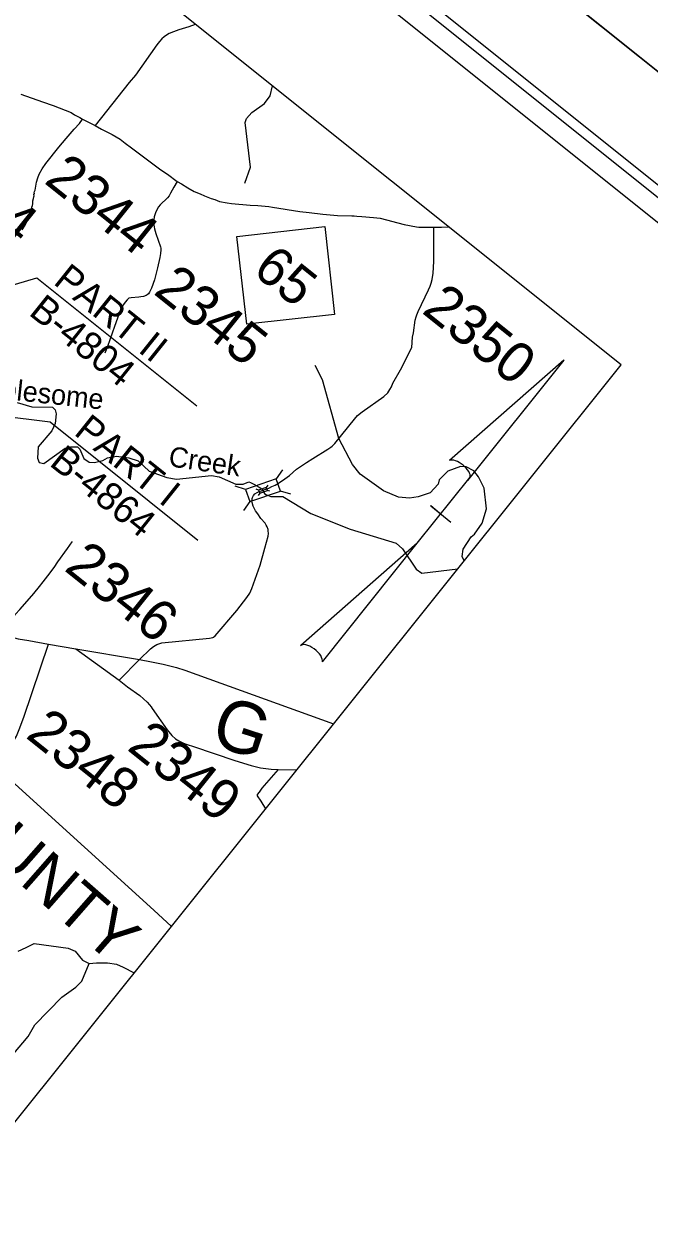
# Model space of a CAD drawing. Extents: x 1730256 to 1738218, y 910410 to 917906.
# Drawn here: x 1734658 to 1734975, y 916477 to 917081 of the extents above; entities that cross this region are included whole.
import ezdxf

# ---------------------------------------------------------------- set-up
doc = ezdxf.new("R2010")
doc.units = 0
for name, color, linetype in [('Old_Level_23', 7, 'Continuous'), ('Old_Level_24', 7, 'Continuous'), ('Old_Level_28', 7, 'Continuous'), ('Old_Level_29', 7, 'Continuous'), ('Old_Level_32', 7, 'Continuous'), ('Old_Level_50', 7, 'Continuous'), ('Old_Level_52', 7, 'Continuous'), ('Old_Level_56', 7, 'Continuous'), ('Old_Level_57', 7, 'Continuous'), ('Old_Level_59', 7, 'Continuous'), ('Old_Level_9', 7, 'Continuous'), ('Prop North Arrow for Plan Sheets CELL', 7, 'Continuous'), ('Sheet Cutting Line CELL', 7, 'Continuous'), ('Sheet Data Field CELL', 7, 'Continuous'), ('Sheet Plot Border Inside CELL', 7, 'Continuous'), ('Sheet Title CELL', 7, 'Continuous')]:
    doc.layers.add(name, color=color, linetype=linetype)

msp = doc.modelspace()

# ---------------------------------------------------------------- linework, layer by layer
at = {"layer": 'Old_Level_24'}
for p, q in [((1734570.37, 916923.86), (1734664.5, 916951.6)), ((1734664.5, 916951.6), (1734745.76, 916886.57)), ((1734645.29, 916881.7), (1734671.38, 916878.41)), ((1734671.38, 916878.41), (1734746.37, 916818.39))]:
    msp.add_line(p, q, dxfattribs=at)
at = {"layer": 'Old_Level_28'}
for p, q in [((1734670.48, 916765.5), (1734684.38, 916763.24)), ((1734684.38, 916763.24), (1734716.61, 916757.8))]:
    msp.add_line(p, q, dxfattribs=at)
for points in [[(1734649.58, 916769.56), (1734651.27, 916769.17), (1734653.25, 916768.74), (1734655.11, 916768.3), (1734660.49, 916767.38), (1734670.48, 916765.5)], [(1734716.61, 916757.8), (1734722.77, 916756.59), (1734728.66, 916755.34), (1734735.44, 916753.62), (1734739.63, 916752.34), (1734815.22, 916725.09)]]:
    msp.add_lwpolyline(points, dxfattribs=at)
at = {"layer": 'Old_Level_29'}
msp.add_line((1734687.79, 917032.17), (1734694.14, 917028.85), dxfattribs=at)
for points in [[(1734656.47, 917044.85), (1734667.42, 917040.88), (1734672.9, 917039.05), (1734682.02, 917035.47), (1734683.76, 917034.39), (1734685.75, 917033.33), (1734686.4, 917033.01), (1734687.79, 917032.17)], [(1734694.14, 917028.85), (1734697.47, 917027.12), (1734702.81, 917024.41), (1734706.94, 917021.89), (1734709.39, 917019.92), (1734712.61, 917017.63), (1734727.58, 917006.42), (1734730.93, 917004.11), (1734735.82, 917000.48)], [(1734735.82, 917000.48), (1734738.04, 916999.28), (1734741.17, 916997.25), (1734744.41, 916995.45), (1734747.4, 916994.22), (1734749.64, 916993.23), (1734753.05, 916991.88), (1734755, 916991.26), (1734757.36, 916990.38), (1734761.15, 916989.56), (1734763.35, 916989.26), (1734772.81, 916988.52), (1734776.74, 916988.29), (1734782.28, 916987.82), (1734784.2, 916987.5), (1734798.14, 916985.3), (1734802.84, 916984.66), (1734809.67, 916983.92), (1734817.25, 916983.26), (1734824.5, 916982.98), (1734825.72, 916983.04), (1734827.04, 916982.92), (1734829.5, 916982.77), (1734835.54, 916982.25), (1734838.76, 916981.78), (1734850.96, 916978.66), (1734857.25, 916977.39), (1734858.43, 916977.25), (1734860.37, 916977.24), (1734863.39, 916977.35), (1734866.02, 916977.35)], [(1734866.02, 916977.35), (1734869.92, 916977.34), (1734873.5, 916977.51)]]:
    msp.add_lwpolyline(points, dxfattribs=at)
at = {"layer": 'Old_Level_32'}
for p, q in [((1734684.38, 916763.24), (1734706.36, 916747.23)), ((1734706.36, 916747.23), (1734716.61, 916757.8))]:
    msp.add_line(p, q, dxfattribs=at)
for points in [[(1734745.1, 917080.26), (1734744.88, 917080.18), (1734741.69, 917079.04), (1734736.73, 917077.49), (1734733.94, 917076.53), (1734731.8, 917075.58), (1734730.38, 917074.8), (1734729.26, 917073.98), (1734727.98, 917072.89), (1734726.8, 917071.53), (1734725.55, 917069.91), (1734714.57, 917054.48), (1734711.49, 917050.65), (1734694.14, 917028.85)], [(1734657.17, 916975.93), (1734658.6, 916978.3), (1734659.79, 916980.86), (1734660.8, 916983.19), (1734661.66, 916985.45), (1734662.08, 916987.4), (1734662.29, 916988.27), (1734662.46, 916989.18), (1734662.62, 916990.57), (1734662.86, 916991.81), (1734663.03, 916992.62), (1734663.17, 916993.27), (1734663.1, 916993.9), (1734663.31, 916994.39), (1734663.29, 916995.08), (1734663.64, 916996.12), (1734664.39, 917000.1), (1734665.13, 917002.25), (1734665.8, 917004.23), (1734667.2, 917006.88), (1734669.07, 917009.64), (1734675.67, 917017.86), (1734679.46, 917022.32), (1734683.54, 917026.98), (1734686.24, 917029.88), (1734687.79, 917032.17)], [(1734735.82, 917000.48), (1734734.14, 916997.57), (1734732.5, 916994.46), (1734731.66, 916993.2), (1734730.94, 916992.25), (1734727.22, 916988.57), (1734726.4, 916987.57), (1734725.47, 916986.12), (1734724.74, 916984.53), (1734724.17, 916982.48), (1734723.91, 916980.75), (1734723.97, 916978.38), (1734724.32, 916976.35), (1734724.95, 916974.04), (1734727.37, 916967.21), (1734727.46, 916966.54), (1734727.48, 916965.69), (1734727.3, 916963.9), (1734726.94, 916961.87), (1734725.86, 916956.68), (1734724.3, 916950.53), (1734722.75, 916946.3), (1734721.98, 916944.61), (1734721.77, 916944.32), (1734721.2, 916943.5), (1734720.55, 916942.88), (1734720.04, 916942.57), (1734718.76, 916942.14), (1734717.32, 916941.86), (1734716.3, 916941.71), (1734712.52, 916941.43), (1734711.33, 916941.19), (1734710.9, 916940.89), (1734710.36, 916940.42), (1734709.42, 916939.27), (1734708.59, 916938), (1734707.79, 916936.52), (1734707.11, 916935.14), (1734706.37, 916933.36), (1734704.02, 916926.76), (1734700.5, 916916.75), (1734699.08, 916913.27)], [(1734779.36, 916843.69), (1734782.29, 916844.78), (1734783.86, 916845.54), (1734785.6, 916846.21), (1734787.8, 916847.57), (1734790.49, 916849.48), (1734792.76, 916851.13), (1734796.45, 916854.46), (1734801.42, 916857.84), (1734804.66, 916859.84), (1734812.33, 916864.58), (1734813.76, 916865.57), (1734814.4, 916866.12), (1734815.77, 916867.51), (1734825.74, 916879.81), (1734827.39, 916881.61), (1734829.68, 916883.49), (1734840.72, 916891.34), (1734842.79, 916893.08), (1734843.72, 916894.81), (1734844.57, 916896.15), (1734845.25, 916898.02), (1734849.09, 916904.76), (1734855, 916916.22), (1734855.27, 916921.51), (1734855.8, 916923.67), (1734856.67, 916930.11), (1734857.07, 916931.72), (1734857.42, 916932.79), (1734858.09, 916934.49), (1734863.39, 916945.52), (1734864.2, 916947.31), (1734864.79, 916948.9), (1734865.21, 916950.69), (1734865.69, 916953.9), (1734866.1, 916959.88), (1734866.02, 916977.35)], [(1734716.61, 916757.8), (1734722.19, 916763.15), (1734723.71, 916764.38), (1734725.49, 916765.37), (1734728.06, 916766.16), (1734752.26, 916768.53), (1734753.84, 916768.92), (1734754.31, 916769.12), (1734755.13, 916769.81), (1734766.14, 916782.63), (1734771.24, 916789.27), (1734772.66, 916791.5), (1734773.71, 916793.75), (1734777.99, 916805.59), (1734780.31, 916814.31), (1734781.92, 916820.33), (1734782.11, 916821.71), (1734782.07, 916823.09), (1734781.91, 916823.85), (1734781.46, 916825.13), (1734781.01, 916826), (1734780.41, 916826.94), (1734778.3, 916829.41), (1734776.7, 916831.66), (1734775.61, 916833.33), (1734774.71, 916834.99), (1734774.41, 916835.57), (1734773.79, 916837.52), (1734773.74, 916838.23), (1734773.82, 916838.99), (1734773.94, 916839.48), (1734774.08, 916840.03), (1734774.52, 916841.05), (1734775.21, 916841.83), (1734776.36, 916842.64), (1734777.41, 916843.08), (1734778.66, 916843.45), (1734779.36, 916843.69)], [(1734649.58, 916769.56), (1734650.6, 916773.17), (1734651.13, 916775.31), (1734652.47, 916778.8), (1734653.04, 916779.81), (1734653.78, 916780.83), (1734655.89, 916783.23), (1734660.86, 916788.67), (1734663.01, 916791.22), (1734665.92, 916794.89), (1734667.71, 916797.15), (1734670.18, 916800.27), (1734673.33, 916804.41), (1734675.28, 916807.28), (1734680.06, 916814.04), (1734682.48, 916817.5), (1734682.49, 916817.63)], [(1734641.87, 916706.48), (1734645.34, 916707.26), (1734648.22, 916709.96), (1734649.41, 916711.45), (1734650.29, 916712.68), (1734651.67, 916714.53), (1734654.31, 916718.84), (1734655.58, 916722.21), (1734657.9, 916728.49), (1734670.48, 916765.5)], [(1734706.36, 916747.23), (1734710.59, 916743.95), (1734716.93, 916739.46), (1734720.52, 916736.09), (1734721.74, 916734.78), (1734722.52, 916733.81), (1734723.15, 916732.91), (1734730.73, 916721.98), (1734733.07, 916719.12), (1734734.98, 916717.5), (1734736.6, 916716.44), (1734738.96, 916715.29), (1734740.95, 916714.57), (1734744.05, 916713.52), (1734765, 916706.43), (1734773.28, 916703.92), (1734778.06, 916702.74), (1734783.53, 916702.03), (1734787.09, 916701.97)], [(1734787.09, 916701.97), (1734778.86, 916692.42), (1734777.46, 916690.47), (1734776.48, 916689.25), (1734776.39, 916688.56), (1734778.22, 916685.86), (1734780.71, 916681.98)], [(1734787.09, 916701.97), (1734796.53, 916701.75)]]:
    msp.add_lwpolyline(points, dxfattribs=at)
at = {"layer": 'Old_Level_50'}
for p, q in [((1734789.28, 916854.02), (1734786.05, 916849.47)), ((1734770.54, 916844.12), (1734765.19, 916845.72)), ((1734781.84, 916846.28), (1734781.04, 916845.14)), ((1734777.16, 916843.8), (1734775.82, 916844.2)), ((1734777.69, 916842.25), (1734776.89, 916841.11)), ((1734782.91, 916843.19), (1734781.57, 916843.59)), ((1734793.54, 916841.67), (1734788.19, 916843.27)), ((1734772.68, 916837.92), (1734769.45, 916833.37))]:
    msp.add_line(p, q, dxfattribs=at)
msp.add_lwpolyline([(1734772.68, 916837.92), (1734788.19, 916843.27), (1734786.05, 916849.47), (1734770.54, 916844.12)], close=True, dxfattribs=at)
msp.add_lwpolyline([(1734777.69, 916842.25), (1734781.57, 916843.59), (1734781.04, 916845.14), (1734777.16, 916843.8), (1734777.69, 916842.25)], dxfattribs=at)
at = {"layer": 'Old_Level_52'}
msp.add_lwpolyline([(1734732.93, 916622.27), (1734723.88, 916630.49), (1734583.09, 916758.4), (1734358.65, 916958.62), (1734222.3, 917078.43)], dxfattribs=at)
at = {"layer": 'Old_Level_59'}
for points in [[(1734770.17, 916999.54), (1734773.05, 917007.71), (1734770.31, 917030.4), (1734770.98, 917032.52), (1734773.63, 917035.43), (1734780.15, 917040.14), (1734783.01, 917043.96), (1734784.19, 917048.99)], [(1734881.4, 916807.8), (1734880.55, 916809.98), (1734880.92, 916813.73), (1734885, 916820.05), (1734886.81, 916821.32), (1734890.64, 916826.99), (1734892.84, 916834.34), (1734891.65, 916844.74), (1734888.82, 916850.52), (1734886.46, 916853.56), (1734882.53, 916855.66), (1734879.69, 916855.79), (1734873.13, 916853.36), (1734868.82, 916849.05), (1734868.32, 916846.79), (1734864.16, 916842.35), (1734858.19, 916840.28), (1734853.66, 916839.68), (1734848.13, 916840.13), (1734840.54, 916843.36), (1734828.66, 916851.89), (1734824.8, 916856.71), (1734817.82, 916869.91), (1734809.59, 916899.75), (1734805.84, 916907.04)], [(1734654.66, 916888.29), (1734662.01, 916886.11), (1734672.56, 916885.85), (1734673.85, 916884.46), (1734674.34, 916882.44), (1734673.84, 916877.52), (1734672.14, 916873.8), (1734665.24, 916865.67), (1734664.94, 916860.05), (1734665.76, 916857.75), (1734668.05, 916857.24), (1734678.95, 916865.03), (1734681.69, 916865.73), (1734685.22, 916865.78), (1734686.4, 916864.58), (1734688.36, 916859.74), (1734691.19, 916857.91), (1734693.77, 916857.79), (1734698.07, 916858.79), (1734700.48, 916860.09), (1734704.96, 916860.96), (1734711.3, 916860.15), (1734716.01, 916858.68), (1734721.6, 916853.38)], [(1734721.6, 916853.38), (1734730.51, 916850.11), (1734735.47, 916849.28), (1734753.2, 916851.26), (1734757.11, 916850.46), (1734765.66, 916846.74), (1734769.24, 916846.86), (1734772.22, 916847.9), (1734773.05, 916847.69), (1734774.71, 916846.81), (1734777.46, 916845.27), (1734778.7, 916844.38), (1734779.36, 916843.69), (1734779.7, 916842.92), (1734780.17, 916841.99), (1734780.76, 916841.47), (1734783.36, 916840.45), (1734789.41, 916840.61), (1734803.6, 916831.97), (1734823.7, 916823.96), (1734846.94, 916816.87), (1734850.24, 916814), (1734857.09, 916803.59), (1734860.05, 916801.64), (1734878.26, 916803.87)], [(1734655.08, 916609.68), (1734659.11, 916611.61), (1734663.18, 916613.54), (1734680.42, 916611.17), (1734684.02, 916609.62), (1734687.7, 916605.06), (1734691.21, 916603.36)], [(1734691.21, 916603.36), (1734694.92, 916603.72), (1734700.4, 916603.83), (1734705.03, 916603.08), (1734708.39, 916601.51), (1734713.96, 916598.63)], [(1734635.13, 916539.7), (1734638.51, 916541.78), (1734642.72, 916545.84), (1734660.16, 916566.37), (1734663.48, 916572.28), (1734677.19, 916586.38), (1734684.29, 916591.32), (1734687.4, 916594.39), (1734691.21, 916603.36)]]:
    msp.add_lwpolyline(points, dxfattribs=at)
at = {"layer": 'Old_Level_9'}
msp.add_lwpolyline([(1734766.13, 916972.6), (1734810.78, 916977.56), (1734815.74, 916932.9), (1734771.08, 916927.95)], close=True, dxfattribs=at)
at = {"layer": 'Prop North Arrow for Plan Sheets CELL'}
for p, q in [((1734874.05, 916858.89), (1734932.06, 916909.84)), ((1734932.13, 916909.79), (1734883.13, 916848.57)), ((1734932.13, 916909.79), (1734932.06, 916909.84)), ((1734932.13, 916909.79), (1734932.06, 916909.84)), ((1734857.71, 916816.81), (1734884.57, 916850.37)), ((1734883.13, 916848.57), (1734884.52, 916850.3)), ((1734864.48, 916835.77), (1734864.42, 916835.82)), ((1734869.03, 916832.13), (1734864.48, 916835.77)), ((1734864.54, 916835.72), (1734874.79, 916827.52)), ((1734857.71, 916816.81), (1734798.59, 916764.85)), ((1734809.55, 916756.5), (1734857.71, 916816.81))]:
    msp.add_line(p, q, dxfattribs=at)
for centre, start_param, end_param in [((1734878.84, 916854.01), 0.216388, 2.908219), ((1734803.84, 916760.3), 0.201328, 3.141593)]:
    msp.add_ellipse(centre, major_axis=(5.39, -4.37), ratio=0.461098, start_param=start_param, end_param=end_param, dxfattribs=at)
at = {"layer": 'Sheet Cutting Line CELL'}
msp.add_line((1734139.89, 917728.48), (1736769.47, 915624.02), dxfattribs=at)
at = {"layer": 'Sheet Data Field CELL'}
msp.add_lwpolyline([(1736769.47, 915624.02), (1734139.89, 917728.48), (1732765.26, 916010.84), (1735394.84, 913906.38)], close=True, dxfattribs=at)
at = {"layer": 'Sheet Plot Border Inside CELL'}
msp.add_lwpolyline([(1732813.6, 916029.63), (1735415.85, 913947.04), (1736734.39, 915594.59), (1734132.13, 917677.18)], close=True, dxfattribs=at)
at = {"layer": 'Sheet Title CELL'}
for p, q in [((1734961.11, 916907.39), (1734427.31, 917334.59)), ((1734961.11, 916907.39), (1734427.31, 917334.59)), ((1734625.37, 916487.87), (1734961.11, 916907.39)), ((1734625.37, 916487.87), (1734961.11, 916907.39))]:
    msp.add_line(p, q, dxfattribs=at)
for points in [[(1736696.09, 915618.71), (1734385.03, 917468.28)], [(1736682.01, 915617.17), (1734464.69, 917391.69)]]:
    msp.add_lwpolyline(points, dxfattribs=at)

# ---------------------------------------------------------------- texts
at = {"layer": 'Old_Level_23'}
for s, p in [('2904', (1734606.55, 917005.49)), ('2344', (1734667.73, 917000.09)), ('2345', (1734723.22, 916943.81)), ('2350', (1734859.44, 916934.15)), ('2346', (1734677.88, 916803.38)), ('2348', (1734658.33, 916718.49)), ('2349', (1734709.8, 916712.28))]:
    msp.add_text(s, height=20.505, rotation=321.3297, dxfattribs=at).set_placement(p)
at = {"layer": 'Old_Level_24'}
for s, p in [('PART II', (1734672.43, 916948.76)), ('B-4804', (1734659.94, 916933.15)), ('PART I', (1734682.89, 916872.29)), ('B-4864', (1734670.39, 916856.67))]:
    msp.add_text(s, height=14, rotation=321.32968, dxfattribs=at).set_placement(p)
at = {"layer": 'Old_Level_52'}
msp.add_text('GUILFORD  COUNTY', height=23.786, rotation=318.72172, dxfattribs=at).set_placement((1734465.36, 916810.93))
at = {"layer": 'Old_Level_56'}
msp.add_text('G', height=26.25, rotation=341.76897, dxfattribs=at).set_placement((1734751.72, 916715.06))
at = {"layer": 'Old_Level_57'}
for s, height, rotation, p in [('Troublesome', 10.2526, 353.85374, (1734618.34, 916893.22)), ('Creek', 10.253, 351.71429, (1734731.03, 916855.98))]:
    msp.add_text(s, height=height, rotation=rotation, dxfattribs=at).set_placement(p)
at = {"layer": 'Old_Level_9'}
msp.add_text('65', height=19.685, rotation=321.3297, dxfattribs=at).set_placement((1734773.49, 916954.11))

doc.saveas('drawing.dxf')
